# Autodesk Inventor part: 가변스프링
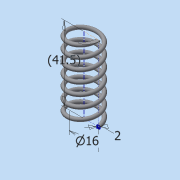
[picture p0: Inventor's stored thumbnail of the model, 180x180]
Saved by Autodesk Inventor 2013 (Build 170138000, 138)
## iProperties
Created: 2018-11
Part Number: 가변스프링
Material: 일반
Document SubType Name: Modeling
Designer: dgall
Density: 1 g/cm^3
Author: dgall
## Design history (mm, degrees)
sketch "스케치1"
  geometry: L1 (0, 0)-(8, 0); L2 (8, 0)-(8, 41.5); L3 (8, 41.5)-(0, 41.5); L4 (0, 41.5)-(0, 0); C1 r 1 at (8, 0)
  constraints: 8 end point, 2 parallel, 1 centre point, 1 coincident, 1 horizontal, 1 perpendicular
  dimensions: "d0" = 41.5 distance of L3.end L1.start (derived); "d1" = 16 diameter of L2 L4; "d2" = 2 diameter of C1
feature "코일1" pitch "d3" = 10; turns "d5" = 7; dims "d4" = 41.5 (= d0), "d6" = 0, angle "d7" = 90 deg, angle "d8" = 90 deg, "d9" = 0, "d10" = 0
node "작업 평면1"
node "작업 평면2"
feature "분할1"
feature "분할2"
node "솔리드1"
